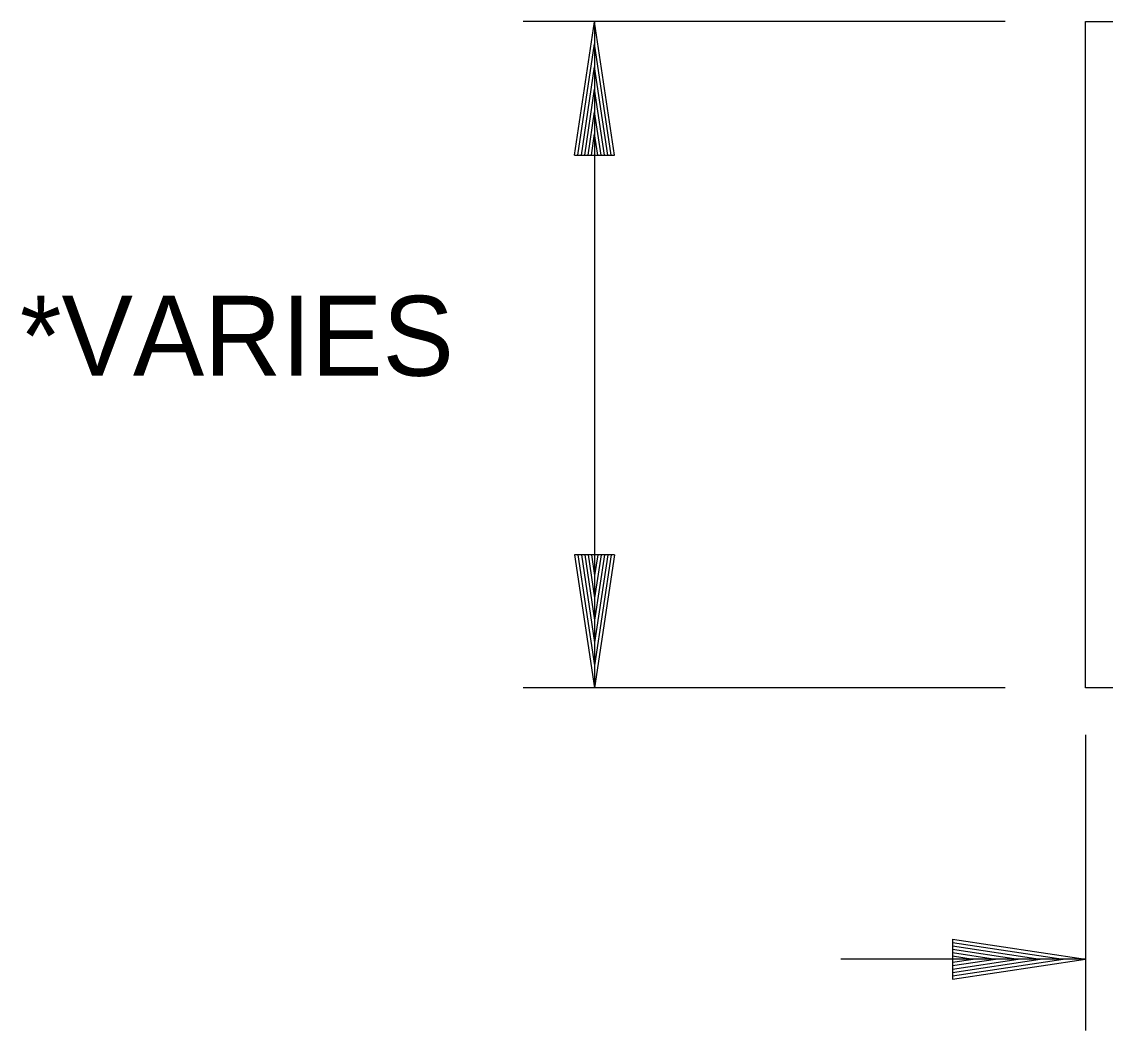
# Model space of a CAD drawing. Extents: x 635488 to 635865, y 290537 to 290973.
# Drawn here: x 635651.61 to 635659.74, y 290605.42 to 290612.99 of the extents above; entities that cross this region are included whole.
import ezdxf

# ---------------------------------------------------------------- set-up
doc = ezdxf.new("R2010")
doc.units = 0
doc.layers.add('Default', color=7, linetype='Continuous')

msp = doc.modelspace()

# ---------------------------------------------------------------- linework, layer by layer
at = {"layer": 'Default'}
for p, q in [((635658.9829, 290612.9873), (635655.3694, 290612.9873)), ((635655.7529, 290611.9859), (635655.9029, 290612.9859)), ((635656.0529, 290611.9859), (635655.9029, 290612.9859)), ((635655.9032, 290612.9873), (635655.9032, 290607.9876)), ((635659.5863, 290607.9876), (635659.5863, 290612.9873)), ((635655.7779, 290611.9859), (635655.9029, 290612.8209)), ((635656.0279, 290611.9859), (635655.9029, 290612.8209)), ((635655.8054, 290611.9859), (635655.9029, 290612.6484)), ((635656.0029, 290611.9859), (635655.9029, 290612.6484)), ((635655.8304, 290611.9859), (635655.9029, 290612.4809)), ((635655.9779, 290611.9859), (635655.9029, 290612.4809)), ((635655.8554, 290611.9859), (635655.9029, 290612.3109)), ((635655.9529, 290611.9859), (635655.9029, 290612.3109)), ((635655.8804, 290611.9859), (635655.9029, 290612.1459)), ((635655.9279, 290611.9859), (635655.9029, 290612.1459)), ((635655.7529, 290611.9859), (635656.0529, 290611.9859)), ((635655.7529, 290608.9861), (635655.9029, 290607.9862)), ((635656.0529, 290608.9861), (635655.7529, 290608.9861)), ((635655.7779, 290608.9861), (635655.9029, 290608.1537)), ((635655.8054, 290608.9861), (635655.9029, 290608.3262)), ((635655.8304, 290608.9861), (635655.9029, 290608.4937)), ((635655.8554, 290608.9861), (635655.9029, 290608.6612)), ((635655.8804, 290608.9861), (635655.9029, 290608.8286)), ((635656.0529, 290608.9861), (635655.9029, 290607.9862)), ((635655.9529, 290608.9861), (635655.9029, 290608.6612)), ((635656.0029, 290608.9861), (635655.9029, 290608.3262)), ((635656.0279, 290608.9861), (635655.9029, 290608.1537)), ((635655.9779, 290608.9861), (635655.9029, 290608.4937)), ((635655.9279, 290608.9861), (635655.9029, 290608.8286)), ((635658.9829, 290607.9876), (635655.3694, 290607.9876)), ((635660.8362, 290607.9876), (635659.5863, 290607.9876)), ((635659.5863, 290607.6342), (635659.5863, 290605.4156)), ((635658.5878, 290606.0988), (635659.5877, 290605.9488)), ((635658.5878, 290606.0988), (635658.5878, 290605.7988)), ((635658.5878, 290606.0738), (635659.4202, 290605.9488)), ((635658.5878, 290606.0488), (635659.2477, 290605.9488)), ((635659.5863, 290605.9497), (635657.7511, 290605.9497)), ((635658.5878, 290606.0238), (635659.0827, 290605.9488)), ((635658.5878, 290605.9988), (635658.9127, 290605.9488)), ((635658.5878, 290605.9738), (635658.7452, 290605.9488)), ((635658.5878, 290605.7988), (635659.5877, 290605.9488)), ((635658.5878, 290605.9013), (635658.9127, 290605.9488)), ((635658.5878, 290605.8488), (635659.2477, 290605.9488)), ((635658.5878, 290605.8238), (635659.4202, 290605.9488)), ((635658.5878, 290605.8738), (635659.0827, 290605.9488)), ((635658.5878, 290605.9263), (635658.7452, 290605.9488))]:
    msp.add_line(p, q, dxfattribs=at)
msp.add_lwpolyline([(635659.5863, 290612.9873), (635750.8305, 290612.9873)], dxfattribs=at)

# ---------------------------------------------------------------- texts
msp.add_text('*VARIES', height=0.6, dxfattribs=at).set_placement((635651.5931, 290610.3292))

doc.saveas('drawing.dxf')
